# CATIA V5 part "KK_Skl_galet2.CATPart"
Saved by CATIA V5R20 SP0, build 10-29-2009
Part number: Skl_galet2
Publications: "Axe_pivot_galet2", "Plan.Ref5", "Point.2", "Plan_Ref1"
Bounding box of the stored display mesh (mm): x -7.5 to 32.5, y 190 to 190, z 15 to 15
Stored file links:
  G:\Khaled_CFAO_2011\ST2M\ST2M_GR2\aandujar\Khaled\CAD_thinkMOTION\KK_Skl_galet2.CATPart
  G:\Khaled_CFAO_2011\ST2M\ST2M_GR2\aandujar\Khaled\CAD_thinkMOTION\KK_Skl_scie_mecanique.CATProduct
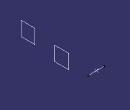
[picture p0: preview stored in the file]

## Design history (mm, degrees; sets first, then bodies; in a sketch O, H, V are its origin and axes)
WSupportSet1: ActiveGrid {3dwsupport RefPoint {point stored without definition}, 3DWOS ({wsupport Support xy-plane, RefPoint {3dwsupport}, GridIn {cartgrid Value 100, Stepbid1 0, Value 100, Stepbid2 0, Direction (1, 0, 0)}, GeometricData ({line type PtDir, Direction (1, 0, 0), Support xy-plane}; {line type PtDir, Direction (0, 1, 0), Support yz-plane})}; {wsupport Support yz-plane, RefPoint {3dwsupport}, GridIn {cartgrid Value 100, Stepbid1 0, Value 100, Stepbid2 0, Direction (0, 1, 0)}, GeometricData ({line type PtDir, Direction (0, 1, 0), Support yz-plane}; {line type PtDir, Direction (0, 0, 1), Support zx-plane})}; {wsupport Support zx-plane, RefPoint {3dwsupport}, GridIn {cartgrid Value 100, Stepbid1 0, Value 100, Stepbid2 0, Direction (0, 0, 1)}, GeometricData ({line type PtDir, Direction (0, 0, 1), Support zx-plane}; {line type PtDir, Direction (1, 0, 0), Support xy-plane})}), GeometricData ({line type PtDir, RefPoint {point stored without definition}, Direction (1, 0, 0), Support xy-plane}; {line type PtDir, RefPoint {point stored without definition}, Direction (0, 1, 0), Support yz-plane}; {line type PtDir, RefPoint {point stored without definition}, Direction (0, 0, 1), Support zx-plane})}
Set1
  Line1 "Axe_pivot_galet2": type Normal, RefPoint Point1, RefSkin Plane2, Start -20, End 20
Set2
  Plane1 "Plan.Ref5": linked copy from another document
  Point1: linked copy from another document
  Plane2 "Plan_Ref1": linked copy from another document
Body1 (main body)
